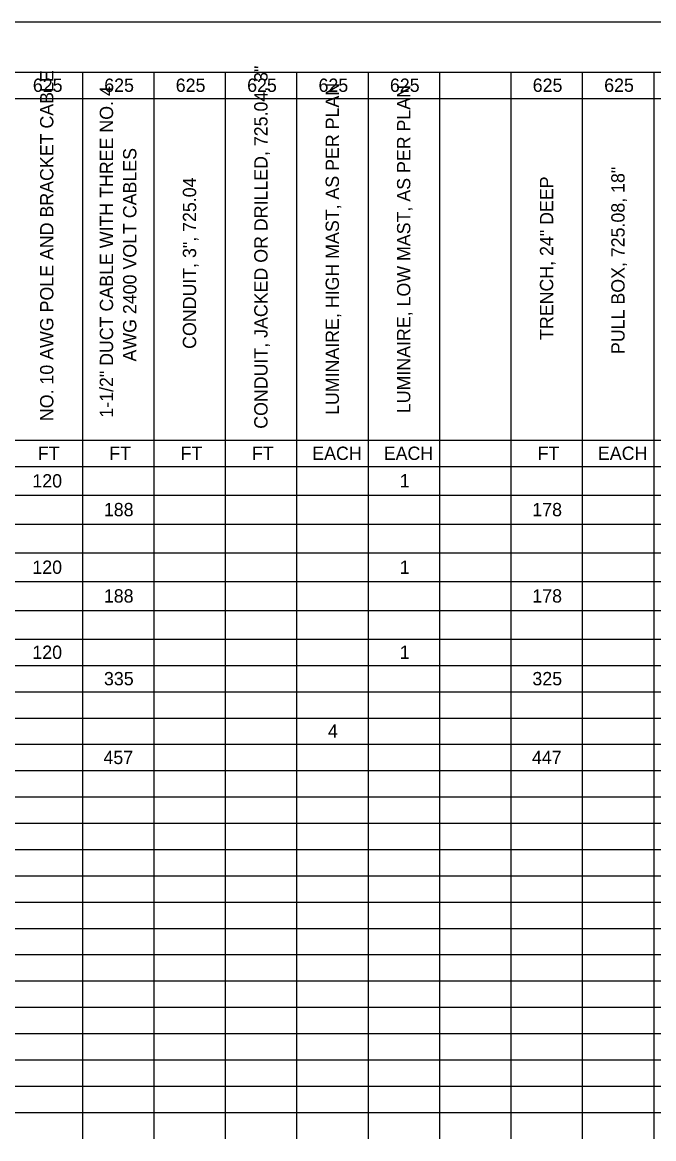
# Model space of a CAD drawing. Extents: x 0 to 34, y 0 to 22.
# Drawn here: x 18.49 to 24.83, y 10.78 to 22 of the extents above; entities that cross this region are included whole.
import ezdxf

# ---------------------------------------------------------------- set-up
doc = ezdxf.new("R2010")
doc.units = 0
for name, color, linetype in [('Default', 7, 'Continuous'), ('SH_Border', 7, 'Continuous'), ('SH_Cut_Line', 7, 'Continuous')]:
    doc.layers.add(name, color=color, linetype=linetype)

msp = doc.modelspace()

# ---------------------------------------------------------------- linework, layer by layer
at = {"layer": 'Default'}
for p, q in [((15.504, 21.5), (21.958, 21.5)), ((19.089, 21.5), (19.089, 21.236)), ((19.807, 21.5), (19.807, 21.236)), ((20.524, 21.5), (20.524, 21.236)), ((21.241, 21.5), (21.241, 21.236)), ((21.958, 21.5), (22.675, 21.5)), ((21.958, 21.5), (21.958, 21.236)), ((22.675, 21.5), (24.827, 21.5)), ((22.675, 21.5), (22.675, 21.236)), ((23.392, 21.5), (23.392, 21.236)), ((24.11, 21.5), (24.11, 21.236)), ((24.827, 21.5), (25.544, 21.5)), ((24.827, 21.5), (24.827, 21.236)), ((15.504, 21.236), (21.958, 21.236)), ((19.089, 21.236), (19.089, 20.972)), ((19.807, 21.236), (19.807, 20.972)), ((20.524, 21.236), (20.524, 20.972)), ((21.241, 21.236), (21.241, 20.972)), ((21.958, 21.236), (22.675, 21.236)), ((21.958, 21.236), (21.958, 20.972)), ((22.675, 21.236), (24.827, 21.236)), ((22.675, 21.236), (22.675, 20.972)), ((23.392, 21.236), (23.392, 20.972)), ((24.11, 21.236), (24.11, 20.972)), ((24.827, 21.236), (25.544, 21.236)), ((24.827, 21.236), (24.827, 20.972)), ((19.089, 20.972), (19.089, 20.707)), ((19.807, 20.972), (19.807, 20.707)), ((20.524, 20.972), (20.524, 20.707)), ((21.241, 20.972), (21.241, 20.707)), ((21.958, 20.972), (21.958, 20.707)), ((22.675, 20.972), (22.675, 20.707)), ((23.392, 20.972), (23.392, 20.707)), ((24.11, 20.972), (24.11, 20.707)), ((24.827, 20.972), (24.827, 20.707)), ((19.089, 20.707), (19.089, 20.443)), ((19.807, 20.707), (19.807, 20.443)), ((20.524, 20.707), (20.524, 20.443)), ((21.241, 20.707), (21.241, 20.443)), ((21.958, 20.707), (21.958, 20.443)), ((22.675, 20.707), (22.675, 20.443)), ((23.392, 20.707), (23.392, 20.443)), ((24.11, 20.707), (24.11, 20.443)), ((24.827, 20.707), (24.827, 20.443)), ((19.089, 20.443), (19.089, 20.179)), ((19.807, 20.443), (19.807, 20.179)), ((20.524, 20.443), (20.524, 20.179)), ((21.241, 20.443), (21.241, 20.179)), ((21.958, 20.443), (21.958, 20.179)), ((22.675, 20.443), (22.675, 20.179)), ((23.392, 20.443), (23.392, 20.179)), ((24.11, 20.443), (24.11, 20.179)), ((24.827, 20.443), (24.827, 20.179)), ((19.089, 20.179), (19.089, 19.915)), ((19.807, 20.179), (19.807, 19.915)), ((20.524, 20.179), (20.524, 19.915)), ((21.241, 20.179), (21.241, 19.915)), ((21.958, 20.179), (21.958, 19.915)), ((22.675, 20.179), (22.675, 19.915)), ((23.392, 20.179), (23.392, 19.915)), ((24.11, 20.179), (24.11, 19.915)), ((24.827, 20.179), (24.827, 19.915)), ((19.089, 19.915), (19.089, 19.651)), ((19.807, 19.915), (19.807, 19.651)), ((20.524, 19.915), (20.524, 19.651)), ((21.241, 19.915), (21.241, 19.651)), ((21.958, 19.915), (21.958, 19.651)), ((22.675, 19.915), (22.675, 19.651)), ((23.392, 19.915), (23.392, 19.651)), ((24.11, 19.915), (24.11, 19.651)), ((24.827, 19.915), (24.827, 19.651)), ((19.089, 19.651), (19.089, 19.122)), ((19.807, 19.651), (19.807, 19.122)), ((20.524, 19.651), (20.524, 19.122)), ((21.241, 19.651), (21.241, 19.122)), ((21.958, 19.651), (21.958, 19.122)), ((22.675, 19.651), (22.675, 19.122)), ((23.392, 19.651), (23.392, 19.122)), ((24.11, 19.651), (24.11, 19.122)), ((24.827, 19.651), (24.827, 19.122)), ((19.089, 19.122), (19.089, 18.329)), ((19.807, 19.122), (19.807, 18.329)), ((20.524, 19.122), (20.524, 18.329)), ((21.241, 19.122), (21.241, 18.329)), ((21.958, 19.122), (21.958, 18.329)), ((22.675, 19.122), (22.675, 18.329)), ((23.392, 19.122), (23.392, 18.329)), ((24.11, 19.122), (24.11, 18.329)), ((24.827, 19.122), (24.827, 18.329)), ((19.089, 18.329), (19.089, 18.065)), ((19.807, 18.329), (19.807, 18.065)), ((20.524, 18.329), (20.524, 18.065)), ((21.241, 18.329), (21.241, 18.065)), ((21.958, 18.329), (21.958, 18.065)), ((22.675, 18.329), (22.675, 18.065)), ((23.392, 18.329), (23.392, 18.065)), ((24.11, 18.329), (24.11, 18.065)), ((24.827, 18.329), (24.827, 18.065)), ((19.089, 18.065), (19.089, 17.537)), ((19.807, 18.065), (19.807, 17.537)), ((20.524, 18.065), (20.524, 17.537)), ((21.241, 18.065), (21.241, 17.537)), ((21.958, 18.065), (21.958, 17.537)), ((22.675, 18.065), (22.675, 17.537)), ((23.392, 18.065), (23.392, 17.537)), ((24.11, 18.065), (24.11, 17.537)), ((24.827, 18.065), (24.827, 17.537)), ((15.504, 17.801), (21.958, 17.801)), ((21.958, 17.801), (22.675, 17.801)), ((22.675, 17.801), (24.827, 17.801)), ((24.827, 17.801), (25.544, 17.801)), ((15.504, 17.537), (21.958, 17.537)), ((19.089, 17.537), (19.089, 17.247)), ((19.807, 17.537), (19.807, 17.247)), ((20.524, 17.537), (20.524, 17.247)), ((21.241, 17.537), (21.241, 17.247)), ((21.958, 17.537), (22.675, 17.537)), ((21.958, 17.537), (21.958, 17.247)), ((22.675, 17.537), (24.827, 17.537)), ((22.675, 17.537), (22.675, 17.247)), ((23.392, 17.537), (23.392, 17.247)), ((24.11, 17.537), (24.11, 17.247)), ((24.827, 17.537), (25.544, 17.537)), ((24.827, 17.537), (24.827, 17.247)), ((15.504, 17.247), (21.958, 17.247)), ((19.089, 17.247), (19.089, 15.801)), ((19.807, 17.247), (19.807, 15.801)), ((20.524, 17.247), (20.524, 15.801)), ((21.241, 17.247), (21.241, 15.801)), ((21.958, 17.247), (22.675, 17.247)), ((21.958, 17.247), (21.958, 15.801)), ((22.675, 17.247), (24.827, 17.247)), ((22.675, 17.247), (22.675, 15.801)), ((23.392, 17.247), (23.392, 15.801)), ((24.11, 17.247), (24.11, 15.801)), ((24.827, 17.247), (25.544, 17.247)), ((24.827, 17.247), (24.827, 15.801)), ((15.504, 16.958), (21.958, 16.958)), ((21.958, 16.958), (22.675, 16.958)), ((22.675, 16.958), (24.827, 16.958)), ((24.827, 16.958), (25.544, 16.958)), ((15.504, 16.669), (21.958, 16.669)), ((21.958, 16.669), (22.675, 16.669)), ((22.675, 16.669), (24.827, 16.669)), ((24.827, 16.669), (25.544, 16.669)), ((15.504, 16.379), (21.958, 16.379)), ((21.958, 16.379), (22.675, 16.379)), ((22.675, 16.379), (24.827, 16.379)), ((24.827, 16.379), (25.544, 16.379)), ((15.504, 16.09), (21.958, 16.09)), ((21.958, 16.09), (22.675, 16.09)), ((22.675, 16.09), (24.827, 16.09)), ((24.827, 16.09), (25.544, 16.09)), ((15.504, 15.801), (21.958, 15.801)), ((19.089, 15.801), (19.089, 15.272)), ((19.807, 15.801), (19.807, 15.272)), ((20.524, 15.801), (20.524, 15.272)), ((21.241, 15.801), (21.241, 15.272)), ((21.958, 15.801), (22.675, 15.801)), ((21.958, 15.801), (21.958, 15.272)), ((22.675, 15.801), (24.827, 15.801)), ((22.675, 15.801), (22.675, 15.272)), ((23.392, 15.801), (23.392, 15.272)), ((24.11, 15.801), (24.11, 15.272)), ((24.827, 15.801), (25.544, 15.801)), ((24.827, 15.801), (24.827, 15.272)), ((15.504, 15.536), (21.958, 15.536)), ((21.958, 15.536), (22.675, 15.536)), ((22.675, 15.536), (24.827, 15.536)), ((24.827, 15.536), (25.544, 15.536)), ((15.504, 15.272), (21.958, 15.272)), ((19.089, 15.272), (19.089, 15.008)), ((19.807, 15.272), (19.807, 15.008)), ((20.524, 15.272), (20.524, 15.008)), ((21.241, 15.272), (21.241, 15.008)), ((21.958, 15.272), (22.675, 15.272)), ((21.958, 15.272), (21.958, 15.008)), ((22.675, 15.272), (24.827, 15.272)), ((22.675, 15.272), (22.675, 15.008)), ((23.392, 15.272), (23.392, 15.008)), ((24.11, 15.272), (24.11, 15.008)), ((24.827, 15.272), (25.544, 15.272)), ((24.827, 15.272), (24.827, 15.008)), ((15.504, 15.008), (21.958, 15.008)), ((19.089, 15.008), (19.089, 14.479)), ((19.807, 15.008), (19.807, 14.479)), ((20.524, 15.008), (20.524, 14.479)), ((21.241, 15.008), (21.241, 14.479)), ((21.958, 15.008), (22.675, 15.008)), ((21.958, 15.008), (21.958, 14.479)), ((22.675, 15.008), (24.827, 15.008)), ((22.675, 15.008), (22.675, 14.479)), ((23.392, 15.008), (23.392, 14.479)), ((24.11, 15.008), (24.11, 14.479)), ((24.827, 15.008), (25.544, 15.008)), ((24.827, 15.008), (24.827, 14.479)), ((15.504, 14.744), (21.958, 14.744)), ((21.958, 14.744), (22.675, 14.744)), ((22.675, 14.744), (24.827, 14.744)), ((24.827, 14.744), (25.544, 14.744)), ((15.504, 14.479), (21.958, 14.479)), ((19.089, 14.479), (19.089, 13.423)), ((19.807, 14.479), (19.807, 13.423)), ((20.524, 14.479), (20.524, 13.423)), ((21.241, 14.479), (21.241, 13.423)), ((21.958, 14.479), (22.675, 14.479)), ((21.958, 14.479), (21.958, 13.423)), ((22.675, 14.479), (24.827, 14.479)), ((22.675, 14.479), (22.675, 13.423)), ((23.392, 14.479), (23.392, 13.423)), ((24.11, 14.479), (24.11, 13.423)), ((24.827, 14.479), (25.544, 14.479)), ((24.827, 14.479), (24.827, 13.423)), ((15.504, 14.215), (21.958, 14.215)), ((21.958, 14.215), (22.675, 14.215)), ((22.675, 14.215), (24.827, 14.215)), ((24.827, 14.215), (25.544, 14.215)), ((15.504, 13.951), (21.958, 13.951)), ((21.958, 13.951), (22.675, 13.951)), ((22.675, 13.951), (24.827, 13.951)), ((24.827, 13.951), (25.544, 13.951)), ((15.504, 13.687), (21.958, 13.687)), ((21.958, 13.687), (22.675, 13.687)), ((22.675, 13.687), (24.827, 13.687)), ((24.827, 13.687), (25.544, 13.687)), ((15.504, 13.423), (21.958, 13.423)), ((19.089, 13.423), (19.089, 13.158)), ((19.807, 13.423), (19.807, 13.158)), ((20.524, 13.423), (20.524, 13.158)), ((21.241, 13.423), (21.241, 13.158)), ((21.958, 13.423), (22.675, 13.423)), ((21.958, 13.423), (21.958, 13.158)), ((22.675, 13.423), (24.827, 13.423)), ((22.675, 13.423), (22.675, 13.158)), ((23.392, 13.423), (23.392, 13.158)), ((24.11, 13.423), (24.11, 13.158)), ((24.827, 13.423), (25.544, 13.423)), ((24.827, 13.423), (24.827, 13.158)), ((15.504, 13.158), (21.958, 13.158)), ((19.089, 13.158), (19.089, 12.894)), ((19.807, 13.158), (19.807, 12.894)), ((20.524, 13.158), (20.524, 12.894)), ((21.241, 13.158), (21.241, 12.894)), ((21.958, 13.158), (22.675, 13.158)), ((21.958, 13.158), (21.958, 12.894)), ((22.675, 13.158), (24.827, 13.158)), ((22.675, 13.158), (22.675, 12.894)), ((23.392, 13.158), (23.392, 12.894)), ((24.11, 13.158), (24.11, 12.894)), ((24.827, 13.158), (25.544, 13.158)), ((24.827, 13.158), (24.827, 12.894)), ((15.504, 12.894), (21.958, 12.894)), ((19.089, 12.894), (19.089, 12.101)), ((19.807, 12.894), (19.807, 12.101)), ((20.524, 12.894), (20.524, 12.101)), ((21.241, 12.894), (21.241, 12.101)), ((21.958, 12.894), (22.675, 12.894)), ((21.958, 12.894), (21.958, 12.101)), ((22.675, 12.894), (24.827, 12.894)), ((22.675, 12.894), (22.675, 12.101)), ((23.392, 12.894), (23.392, 12.101)), ((24.11, 12.894), (24.11, 12.101)), ((24.827, 12.894), (25.544, 12.894)), ((24.827, 12.894), (24.827, 12.101)), ((15.504, 12.63), (21.958, 12.63)), ((21.958, 12.63), (22.675, 12.63)), ((22.675, 12.63), (24.827, 12.63)), ((24.827, 12.63), (25.544, 12.63)), ((15.504, 12.366), (21.958, 12.366)), ((21.958, 12.366), (22.675, 12.366)), ((22.675, 12.366), (24.827, 12.366)), ((24.827, 12.366), (25.544, 12.366)), ((15.504, 12.101), (21.958, 12.101)), ((19.089, 12.101), (19.089, 11.573)), ((19.807, 12.101), (19.807, 11.573)), ((20.524, 12.101), (20.524, 11.573)), ((21.241, 12.101), (21.241, 11.573)), ((21.958, 12.101), (22.675, 12.101)), ((21.958, 12.101), (21.958, 11.573)), ((22.675, 12.101), (24.827, 12.101)), ((22.675, 12.101), (22.675, 11.573)), ((23.392, 12.101), (23.392, 11.573)), ((24.11, 12.101), (24.11, 11.573)), ((24.827, 12.101), (25.544, 12.101)), ((24.827, 12.101), (24.827, 11.573)), ((15.504, 11.837), (21.958, 11.837)), ((21.958, 11.837), (22.675, 11.837)), ((22.675, 11.837), (24.827, 11.837)), ((24.827, 11.837), (25.544, 11.837)), ((15.504, 11.573), (21.958, 11.573)), ((19.089, 11.573), (19.089, 10.78)), ((19.807, 11.573), (19.807, 10.78)), ((20.524, 11.573), (20.524, 10.78)), ((21.241, 11.573), (21.241, 10.78)), ((21.958, 11.573), (22.675, 11.573)), ((21.958, 11.573), (21.958, 10.78)), ((22.675, 11.573), (24.827, 11.573)), ((22.675, 11.573), (22.675, 10.78)), ((23.392, 11.573), (23.392, 10.78)), ((24.11, 11.573), (24.11, 10.78)), ((24.827, 11.573), (25.544, 11.573)), ((24.827, 11.573), (24.827, 10.78)), ((15.504, 11.309), (21.958, 11.309)), ((21.958, 11.309), (22.675, 11.309)), ((22.675, 11.309), (24.827, 11.309)), ((24.827, 11.309), (25.544, 11.309)), ((15.504, 11.045), (21.958, 11.045)), ((21.958, 11.045), (22.675, 11.045)), ((22.675, 11.045), (24.827, 11.045)), ((24.827, 11.045), (25.544, 11.045))]:
    msp.add_line(p, q, dxfattribs=at)
at = {"layer": 'SH_Border'}
msp.add_lwpolyline([(1.5, 21.5), (33.5, 21.5), (33.5, 0.5), (1.5, 0.5)], close=True, dxfattribs=at)
at = {"layer": 'SH_Cut_Line'}
msp.add_lwpolyline([(0, 0), (34, 0), (34, 22), (0, 22)], close=True, dxfattribs=at)

# ---------------------------------------------------------------- texts
at = {"layer": 'Default'}
for s, p in [('CONDUIT, JACKED OR DRILLED, 725.04, 3"', (20.949, 17.915)), ('NO. 10 AWG POLE AND BRACKET CABLE', (18.798, 17.992)), ('1-1/2" DUCT CABLE WITH THREE NO. 4 ', (19.398, 18.027)), ('LUMINAIRE, HIGH MAST, AS PER PLAN', (21.666, 18.054)), ('LUMINAIRE, LOW MAST, AS PER PLAN', (22.383, 18.072)), ('AWG 2400 VOLT CABLES', (19.632, 18.591)), ('PULL BOX, 725.08, 18"', (24.535, 18.666)), ('CONDUIT, 3", 725.04', (20.232, 18.718)), ('TRENCH, 24" DEEP', (23.818, 18.808))]:
    msp.add_text(s, height=0.13368, rotation=90, dxfattribs=at).set_placement(p)
for s, height, p in [('625', 0.1337, (18.592, 21.301)), ('625', 0.1337, (19.309, 21.301)), ('625', 0.1337, (20.027, 21.301)), ('625', 0.1337, (20.744, 21.301)), ('625', 0.1337, (21.461, 21.301)), ('625', 0.1337, (22.178, 21.301)), ('625', 0.1337, (23.612, 21.301)), ('625', 0.1337, (24.33, 21.301)), ('FT', 0.1337, (18.642, 17.602)), ('FT', 0.1337, (19.359, 17.602)), ('FT', 0.1337, (20.076, 17.602)), ('FT', 0.1337, (20.793, 17.602)), ('EACH', 0.1337, (21.398, 17.602)), ('EACH', 0.1337, (22.116, 17.602)), ('FT', 0.1337, (23.662, 17.602)), ('EACH', 0.1337, (24.267, 17.602)), ('120', 0.1337, (18.587, 17.325)), ('1', 0.134, (22.277, 17.325)), ('188', 0.1337, (19.305, 17.036)), ('178', 0.1337, (23.608, 17.036)), ('120', 0.1337, (18.587, 16.457)), ('1', 0.134, (22.277, 16.457)), ('188', 0.1337, (19.305, 16.168)), ('178', 0.1337, (23.608, 16.168)), ('120', 0.1337, (18.587, 15.602)), ('1', 0.134, (22.277, 15.602)), ('335', 0.1337, (19.306, 15.337)), ('325', 0.1337, (23.609, 15.337)), ('4', 0.134, (21.555, 14.809)), ('457', 0.1337, (19.301, 14.545)), ('447', 0.1337, (23.604, 14.545))]:
    msp.add_text(s, height=height, dxfattribs=at).set_placement(p)

doc.saveas('drawing.dxf')
